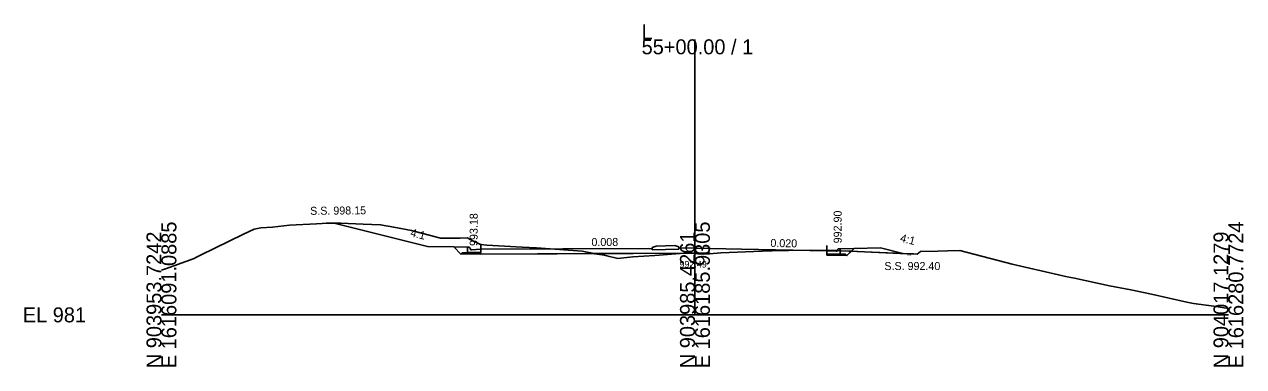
# Model space of a CAD drawing. Extents: x 1009 to 7438, y -1586 to 7964.
# Drawn here: x 5009.2 to 5237.7, y 2914 to 2978.2 of the extents above; entities that cross this region are included whole.
import ezdxf

# ---------------------------------------------------------------- set-up
doc = ezdxf.new("R2010")
doc.units = 0
for name, color, linetype in [('Exist Cross Section Cell', 7, 'Continuous'), ('Exist XS Center Line Elevation Label', 7, 'Continuous'), ('Exist XS Ground Line', 7, 'Continuous'), ('Prop XS Dump Level', 7, 'Continuous'), ('Prop XS Earthwork Shape', 7, 'Continuous'), ('Prop XS EOT Tick Mark', 7, 'Continuous'), ('Prop XS Finish Grade', 7, 'Continuous'), ('Prop XS Finish Grade CurbGutter', 7, 'Continuous'), ('Prop XS Finish Grade Earthwork', 7, 'Continuous'), ('Prop XS Finish Grade Pavement', 7, 'Continuous'), ('Prop XS Hydro Elevations', 7, 'Continuous'), ('Prop XS Pvmt Edge Slope', 7, 'Continuous'), ('Prop XS SE Text', 7, 'Continuous'), ('Prop XS Side Slope Text', 7, 'Continuous'), ('Prop XS SS Elevation Text', 7, 'Continuous'), ('Prop XS Subgrade CurbGutter', 7, 'Continuous'), ('Prop XS Subgrade Earthwork', 7, 'Continuous')]:
    doc.layers.add(name, color=color, linetype=linetype)

msp = doc.modelspace()

# ---------------------------------------------------------------- linework, layer by layer
at = {"layer": 'Exist Cross Section Cell'}
for p, q in [((5134.89, 2923.73), (5134.89, 2975.35)), ((5034.89, 2923.73), (5134.89, 2923.73)), ((5134.89, 2923.73), (5234.89, 2923.73))]:
    msp.add_line(p, q, dxfattribs=at)
at = {"layer": 'Exist XS Ground Line'}
for p, q in [((5050.24, 2938.84), (5052.29, 2939.8)), ((5052.29, 2939.8), (5053.53, 2940.04)), ((5053.53, 2940.04), (5055.7, 2940.14)), ((5055.7, 2940.14), (5058.87, 2940.52)), ((5058.87, 2940.52), (5063.94, 2940.79)), ((5063.94, 2940.79), (5065.02, 2940.85)), ((5065.02, 2940.85), (5065.75, 2940.9)), ((5065.75, 2940.9), (5066.38, 2940.92)), ((5066.38, 2940.92), (5068.54, 2940.94)), ((5068.54, 2940.94), (5072.69, 2940.74)), ((5072.69, 2940.74), (5075.97, 2940.62)), ((5075.97, 2940.62), (5078.44, 2940.15)), ((5078.44, 2940.15), (5081.74, 2939.55)), ((5081.74, 2939.55), (5087.17, 2938.07)), ((5042.21, 2934.89), (5050.24, 2938.84)), ((5087.17, 2938.07), (5090.91, 2938.11)), ((5090.91, 2938.11), (5092.24, 2938.15)), ((5092.24, 2938.15), (5092.64, 2937.94)), ((5092.64, 2937.94), (5094.72, 2936.91)), ((5094.72, 2936.91), (5095.85, 2936.81)), ((5095.85, 2936.81), (5102.48, 2936.44)), ((5041.01, 2934.3), (5041.35, 2934.47)), ((5041.35, 2934.47), (5042.21, 2934.89)), ((5102.48, 2936.44), (5105.21, 2936.3)), ((5105.21, 2936.3), (5113.73, 2935.68)), ((5113.73, 2935.68), (5116.09, 2935.18)), ((5116.09, 2935.18), (5117.96, 2934.94)), ((5117.96, 2934.94), (5118.4, 2934.8)), ((5118.4, 2934.8), (5120.45, 2934.32)), ((5120.45, 2934.32), (5123.22, 2934.63)), ((5123.22, 2934.63), (5127.37, 2934.85)), ((5127.37, 2934.85), (5133.68, 2935.36)), ((5133.68, 2935.36), (5134.89, 2935.22)), ((5134.89, 2935.22), (5135.96, 2935.09)), ((5135.96, 2935.09), (5137.62, 2935.19)), ((5137.62, 2935.19), (5139.74, 2935.38)), ((5139.74, 2935.38), (5147.5, 2935.66)), ((5147.5, 2935.66), (5151.33, 2935.77)), ((5151.33, 2935.77), (5152.43, 2935.78)), ((5152.43, 2935.78), (5156.81, 2935.85)), ((5156.81, 2935.85), (5161.23, 2935.76)), ((5161.23, 2935.76), (5162.29, 2935.74)), ((5162.29, 2935.74), (5166.66, 2935.55)), ((5166.66, 2935.55), (5174.69, 2935.19)), ((5174.69, 2935.19), (5175.84, 2935.15)), ((5175.84, 2935.15), (5176.52, 2935.12)), ((5176.52, 2935.12), (5177.19, 2935.6)), ((5177.19, 2935.6), (5180.39, 2935.68)), ((5180.39, 2935.68), (5182.22, 2935.75)), ((5182.22, 2935.75), (5184.55, 2935.78)), ((5184.55, 2935.78), (5194.35, 2933.22)), ((5034.89, 2932.1), (5035.63, 2932.37)), ((5035.63, 2932.37), (5041.01, 2934.3)), ((5194.35, 2933.22), (5196.76, 2932.65)), ((5196.76, 2932.65), (5200.59, 2931.8)), ((5200.59, 2931.8), (5204.66, 2930.87)), ((5204.66, 2930.87), (5206.02, 2930.58)), ((5206.02, 2930.58), (5212.57, 2929.18)), ((5212.57, 2929.18), (5216.57, 2928.4)), ((5216.57, 2928.4), (5220.47, 2927.63)), ((5220.47, 2927.63), (5227.11, 2926.1)), ((5227.11, 2926.1), (5228.37, 2925.88)), ((5228.37, 2925.88), (5232.14, 2925.35)), ((5232.14, 2925.35), (5234.89, 2924.94))]:
    msp.add_line(p, q, dxfattribs=at)
at = {"layer": 'Prop XS Dump Level'}
for p, q in [((5110.14, 2936.09), (5126.14, 2936.17)), ((5110.14, 2936.09), (5126.14, 2936.17)), ((5134.89, 2936.24), (5143.64, 2936.07)), ((5134.89, 2936.24), (5143.64, 2936.07)), ((5143.64, 2936.07), (5159.64, 2935.75)), ((5143.64, 2936.07), (5159.64, 2935.75))]:
    msp.add_line(p, q, dxfattribs=at)
at = {"layer": 'Prop XS Earthwork Shape'}
for points in [[(5092.64, 2937.94), (5094.72, 2936.91), (5095.85, 2936.81), (5102.48, 2936.44), (5105.21, 2936.3), (5113.73, 2935.68), (5115.99, 2935.2), (5094.76, 2935.09), (5094.76, 2935.18), (5091.01, 2935.12), (5091.26, 2935.38), (5092.26, 2935.39), (5094.76, 2935.43), (5094.76, 2936.01), (5093.01, 2935.91), (5092.88, 2935.94), (5092.79, 2936.03), (5092.72, 2936.28), (5092.63, 2936.37), (5092.51, 2936.4), (5092.26, 2936.4), (5089.68, 2936.45), (5084.76, 2936.56), (5067.28, 2940.93), (5068.54, 2940.94), (5072.69, 2940.74), (5075.97, 2940.62), (5078.44, 2940.15), (5081.74, 2939.55), (5087.17, 2938.07), (5090.91, 2938.11), (5092.24, 2938.15)], [(5091.26, 2935.38), (5091.01, 2935.12), (5089.68, 2936.45), (5092.26, 2936.4), (5092.26, 2935.39)], [(5092.51, 2936.4), (5092.63, 2936.37), (5092.72, 2936.28), (5092.79, 2936.03), (5092.88, 2935.94), (5093.01, 2935.91), (5094.76, 2936.01), (5094.76, 2935.43), (5092.26, 2935.39), (5092.26, 2936.4)], [(5118.4, 2934.8), (5120.45, 2934.32), (5123.22, 2934.63), (5127.37, 2934.85), (5132.85, 2935.29), (5115.99, 2935.2), (5116.09, 2935.18), (5117.96, 2934.94)], [(5133.68, 2935.36), (5134.19, 2935.3), (5132.85, 2935.29)], [(5135.96, 2935.09), (5137.62, 2935.19), (5137.62, 2935.32), (5134.19, 2935.3), (5134.89, 2935.22)], [(5159.64, 2935.79), (5161.23, 2935.76), (5161.61, 2935.76), (5161.52, 2935.67), (5161.39, 2935.64), (5159.64, 2935.75)], [(5159.64, 2935.17), (5162.14, 2935.12), (5162.14, 2935.74), (5161.61, 2935.76), (5161.52, 2935.67), (5161.39, 2935.64), (5159.64, 2935.75)], [(5159.64, 2935.17), (5162.14, 2935.12), (5163.14, 2935.1), (5163.39, 2934.84), (5159.64, 2934.92)], [(5162.14, 2935.74), (5162.29, 2935.74), (5164.21, 2935.66), (5163.39, 2934.84), (5163.14, 2935.1), (5162.14, 2935.12)], [(5164.21, 2935.66), (5166.66, 2935.55), (5173.87, 2935.23), (5169.64, 2936.29), (5164.73, 2936.18)]]:
    msp.add_lwpolyline(points, close=True, dxfattribs=at)
at = {"layer": 'Prop XS EOT Tick Mark'}
for p, q in [((5094.76, 2936.01), (5094.76, 2937.01)), ((5159.64, 2935.75), (5159.64, 2936.75))]:
    msp.add_line(p, q, dxfattribs=at)
at = {"layer": 'Prop XS Finish Grade'}
for p, q in [((5092.26, 2936.4), (5089.68, 2936.45)), ((5162.14, 2936.13), (5164.73, 2936.18))]:
    msp.add_line(p, q, dxfattribs=at)
at = {"layer": 'Prop XS Finish Grade CurbGutter'}
for p, q in [((5127.65, 2936.59), (5131.15, 2936.72)), ((5131.89, 2936.47), (5131.14, 2936.72)), ((5092.26, 2936.4), (5092.51, 2936.4)), ((5092.51, 2936.4), (5092.63, 2936.37)), ((5092.72, 2936.28), (5092.63, 2936.37)), ((5092.79, 2936.03), (5092.72, 2936.28)), ((5092.88, 2935.94), (5092.79, 2936.03)), ((5093.01, 2935.91), (5092.88, 2935.94)), ((5094.76, 2936.01), (5093.01, 2935.91)), ((5126.89, 2936.35), (5127.65, 2936.59)), ((5126.89, 2936.18), (5126.89, 2936.35)), ((5131.89, 2936.3), (5131.89, 2936.47)), ((5159.64, 2935.75), (5161.39, 2935.64)), ((5161.39, 2935.64), (5161.52, 2935.67)), ((5161.52, 2935.67), (5161.61, 2935.76)), ((5161.61, 2935.76), (5161.68, 2936.01)), ((5161.68, 2936.01), (5161.77, 2936.1)), ((5161.89, 2936.13), (5161.77, 2936.1)), ((5162.14, 2936.13), (5161.89, 2936.13))]:
    msp.add_line(p, q, dxfattribs=at)
at = {"layer": 'Prop XS Finish Grade Earthwork'}
for p, q in [((5084.76, 2936.56), (5067.28, 2940.93)), ((5089.68, 2936.45), (5084.76, 2936.56)), ((5164.73, 2936.18), (5169.64, 2936.29)), ((5169.64, 2936.29), (5173.87, 2935.23))]:
    msp.add_line(p, q, dxfattribs=at)
at = {"layer": 'Prop XS Finish Grade Pavement'}
for p, q in [((5094.76, 2936.01), (5126.89, 2936.18)), ((5131.89, 2936.3), (5143.64, 2936.07)), ((5143.64, 2936.07), (5159.64, 2935.75))]:
    msp.add_line(p, q, dxfattribs=at)
at = {"layer": 'Prop XS Pvmt Edge Slope'}
for p, q in [((5091.26, 2935.38), (5091.01, 2935.12)), ((5092.26, 2935.39), (5091.26, 2935.38)), ((5162.14, 2935.12), (5163.14, 2935.1)), ((5163.14, 2935.1), (5163.39, 2934.84))]:
    msp.add_line(p, q, dxfattribs=at)
at = {"layer": 'Prop XS Subgrade CurbGutter'}
for p, q in [((5092.26, 2935.39), (5092.26, 2936.4)), ((5094.76, 2935.43), (5092.26, 2935.39)), ((5094.76, 2936.01), (5094.76, 2935.43)), ((5126.89, 2936.18), (5126.89, 2935.93)), ((5126.89, 2935.93), (5131.89, 2936.05)), ((5131.89, 2936.3), (5131.89, 2936.05)), ((5159.64, 2935.75), (5159.64, 2935.17)), ((5159.64, 2935.17), (5162.14, 2935.12)), ((5162.14, 2935.12), (5162.14, 2936.13))]:
    msp.add_line(p, q, dxfattribs=at)
at = {"layer": 'Prop XS Subgrade Earthwork'}
for p, q in [((5091.01, 2935.12), (5089.68, 2936.45)), ((5094.76, 2935.18), (5091.01, 2935.12)), ((5137.62, 2935.32), (5094.75, 2935.09)), ((5094.76, 2935.09), (5094.76, 2935.18)), ((5137.62, 2935.19), (5137.62, 2935.32)), ((5159.64, 2934.92), (5159.64, 2935.79)), ((5159.64, 2934.92), (5163.39, 2934.84)), ((5163.39, 2934.84), (5164.73, 2936.18))]:
    msp.add_line(p, q, dxfattribs=at)

# ---------------------------------------------------------------- texts
at = {"layer": 'Exist Cross Section Cell'}
for s, p in [('L', (5124.89, 2975.35)), ('55+00.00 / 1', (5124.89, 2972.55)), ('EL 981', (5008.89, 2922.33))]:
    msp.add_text(s, height=2.8, dxfattribs=at).set_placement(p)
for s, p in [('N 903953.7242', (5034.89, 2913.73)), ('E 1616091.0885', (5037.69, 2913.73)), ('N 903985.4261', (5134.89, 2913.73)), ('E 1616185.9305', (5137.69, 2913.73)), ('N 904017.1279', (5234.89, 2913.73)), ('E 1616280.7724', (5237.69, 2913.73))]:
    msp.add_text(s, height=2.8, rotation=90, dxfattribs=at).set_placement(p)
at = {"layer": 'Exist XS Center Line Elevation Label'}
msp.add_text('992.49', height=1.25, dxfattribs=at).set_placement((5131.99, 2932.59))
at = {"layer": 'Prop XS Dump Level'}
for p in [(5135.96, 2934.79), (5135.96, 2934.79), (5135.96, 2934.79), (5174.69, 2934.89)]:
    msp.add_text('Eop', height=0.3, dxfattribs=at).set_placement(p)
at = {"layer": 'Prop XS Hydro Elevations'}
for s, p in [('993.18', (5094.17, 2936.64)), ('992.90', (5162.39, 2937.13))]:
    msp.add_text(s, height=1.5, rotation=90, dxfattribs=at).set_placement(p)
at = {"layer": 'Prop XS SE Text'}
for s, rotation, p in [('0.008', 0.3003, (5115.49, 2936.62)), ('0.020', 358.8542, (5149.02, 2936.46))]:
    msp.add_text(s, height=1.5, rotation=rotation, dxfattribs=at).set_placement(p)
at = {"layer": 'Prop XS Side Slope Text'}
for p in [(5081.45, 2938.47), (5173.26, 2937.47)]:
    msp.add_text('4:1', height=1.5, rotation=345.9638, dxfattribs=at).set_placement(p)
at = {"layer": 'Prop XS SS Elevation Text'}
msp.add_text('S.S. 998.15', height=1.5, rotation=0.5729, dxfattribs=at).set_placement((5062.77, 2942.47))
msp.add_text('S.S. 992.40', height=1.5, dxfattribs=at).set_placement((5170.4, 2932.13))

doc.saveas('drawing.dxf')
